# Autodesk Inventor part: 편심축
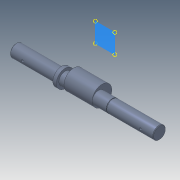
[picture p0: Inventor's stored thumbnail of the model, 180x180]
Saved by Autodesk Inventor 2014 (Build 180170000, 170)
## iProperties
Manager: 한국ATC센터
Company: 한국ATC센터
Created: 2014-10
Part Number: 편심축
Document SubType Name: Modeling
Designer: 한국ATC센터
Density: 7.86 g/cm^3
Material: 강, 연강
Mass: 1420.78 g
Surface Area: 286.549 cm^2
Volume: 180.761 cm^3
Appearance: 강철
Author: KYOUNG IL JANG
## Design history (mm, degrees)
sketch "스케치1"
  geometry: L1 (-142, 0)-(142, 0); L2 (-142, 0)-(-142, 12.5); L3 (-142, 12.5)-(-52, 12.5); L4 (-52, 12.5)-(-52, 17.5); L5 (-52, 17.5)-(-45, 17.5); L6 (-45, 17.5)-(-45, 12.5); L7 (-45, 12.5)-(48.65, 12.5); L8 (48.65, 12.5)-(48.65, 11.95); L9 (48.65, 11.95)-(50, 11.95); L10 (50, 11.95)-(50, 12.5); L11 (50, 12.5)-(142, 12.5); L12 (142, 12.5)-(142, 0); L13 (109, 12.5)-(109, 9.1); L14 (109, 9.1)-(134, 9.1); L15 (134, 9.1)-(134, 12.5); L16 (117, -12.5)-(119.5, -12.5); L17 (119.5, -12.5)-(117, -10); L18 (117, -10)-(117, -12.5); L19 (-109, 12.5)-(-109, 9.1); L20 (-109, 9.1)-(-134, 9.1); L21 (-134, 9.1)-(-134, 12.5); L22 (-117, -12.5)-(-117, -10); L23 (-117, -10)-(-114.5, -12.5); L24 (-114.5, -12.5)-(-117, -12.5); 2 further points
  constraints: 48 end point, 11 parallel, 8 perpendicular, 5 collinear, 4 point on line, 1 coincident, 1 horizontal, 1 midpoint, 1 vertical
  dimensions: "d0" = 284 distance of L1.start L1.end (derived); "d1" = 25 diameter of L3 L1; "d2" = 35 diameter of L5 L1; "d3" = 90 distance of L2.end L3.end; "d4" = 187 distance between parallel lines of L12 L6; "d6" = 1.35 distance of L8.end L9.end; "d7" = 23.9 diameter of L9 L1; "d8" = 3.4 distance between parallel lines of L14 L11; "d9" = 8 distance between parallel lines of L15 L12; "d10" = 25 distance of L13.end L14.end; "d11" = 25 diameter of L16 L1 (= d1); "d12" = 25 distance from line of L12 L16.start; "d13" = 45 deg angle of L17 L18; "d14" = 5 diameter of L16.end L18; "d27" = 92 distance between parallel lines of L10 L12; "d32" = 7 distance of L4.end L5.end; "d33" = 8 distance between parallel lines of L2 L21; "d34" = 25 distance between parallel lines of L21 L19; "d35" = 3.4 distance between parallel lines of L3 L20; "d36" = 25 distance from line of L22.start L2; "d37" = 5 diameter of L23.end L22
revolve "회전1" stored, may be unused: angle "d15" = 90 deg
revolve "회전2" stored, may be unused: angle "d16" = 90 deg
revolve "회전3" stored, may be unused: angle "d38" = 90 deg
extrude "돌출1" cut sketch "스케치1" stored distance "d17" = 8; taper "d18" = 0 deg
fillet "모깎기1" dims "d19" = 4
node "작업 평면1"
sketch "스케치2"
  geometry: C1 r 12.5 at (0, 0) reference; C2 r 19.5 at (0, 7); 1 further point
  constraints: 1 centre point, 1 tangent, 1 vertical alignment
  dimensions: "d21" = 7 distance of point (0, 0) C2.centre; "d30" = 39 diameter of C2 (derived)
extrude "돌출2" join sketch "스케치2" distance "d22" = 56; taper "d23" = 0 deg
chamfer "모따기1" distance "d24" = 1; stored, may be unused: second distance "d25" = 2, angle "d26" = 45 deg
node "솔리드1"
other parameters: "d20" = 16
